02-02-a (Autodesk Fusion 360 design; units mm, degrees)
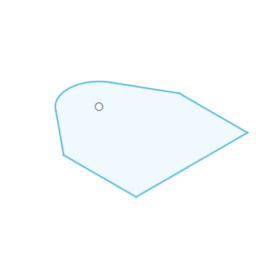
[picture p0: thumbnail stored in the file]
sketch "スケッチ" plane through (0, 0, 0) normal (0, 1, 0) x axis (1, 0, 0)
  line L1 (-4.2557, 35.2477) -> (-30.8824, 20.0622)
  line L2 (37.3484, 35.2477) -> (-4.2557, 35.2477)
  line L3 (37.3484, -32.5669) -> (37.3484, 35.2477)
  line L4 (-6.752, -32.5669) -> (37.3484, -32.5669)
  line L5 (-32.5465, -11.5569) -> (-6.752, -32.5669)
  arc A1 centre (-21.5612, 3.7183) radius 18.8151 clockwise from (-32.5465, -11.5569) to (-30.8824, 20.0622)
  horizontal L2
  perpendicular L2 L3
  perpendicular L3 L4
  tangent L1 A1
